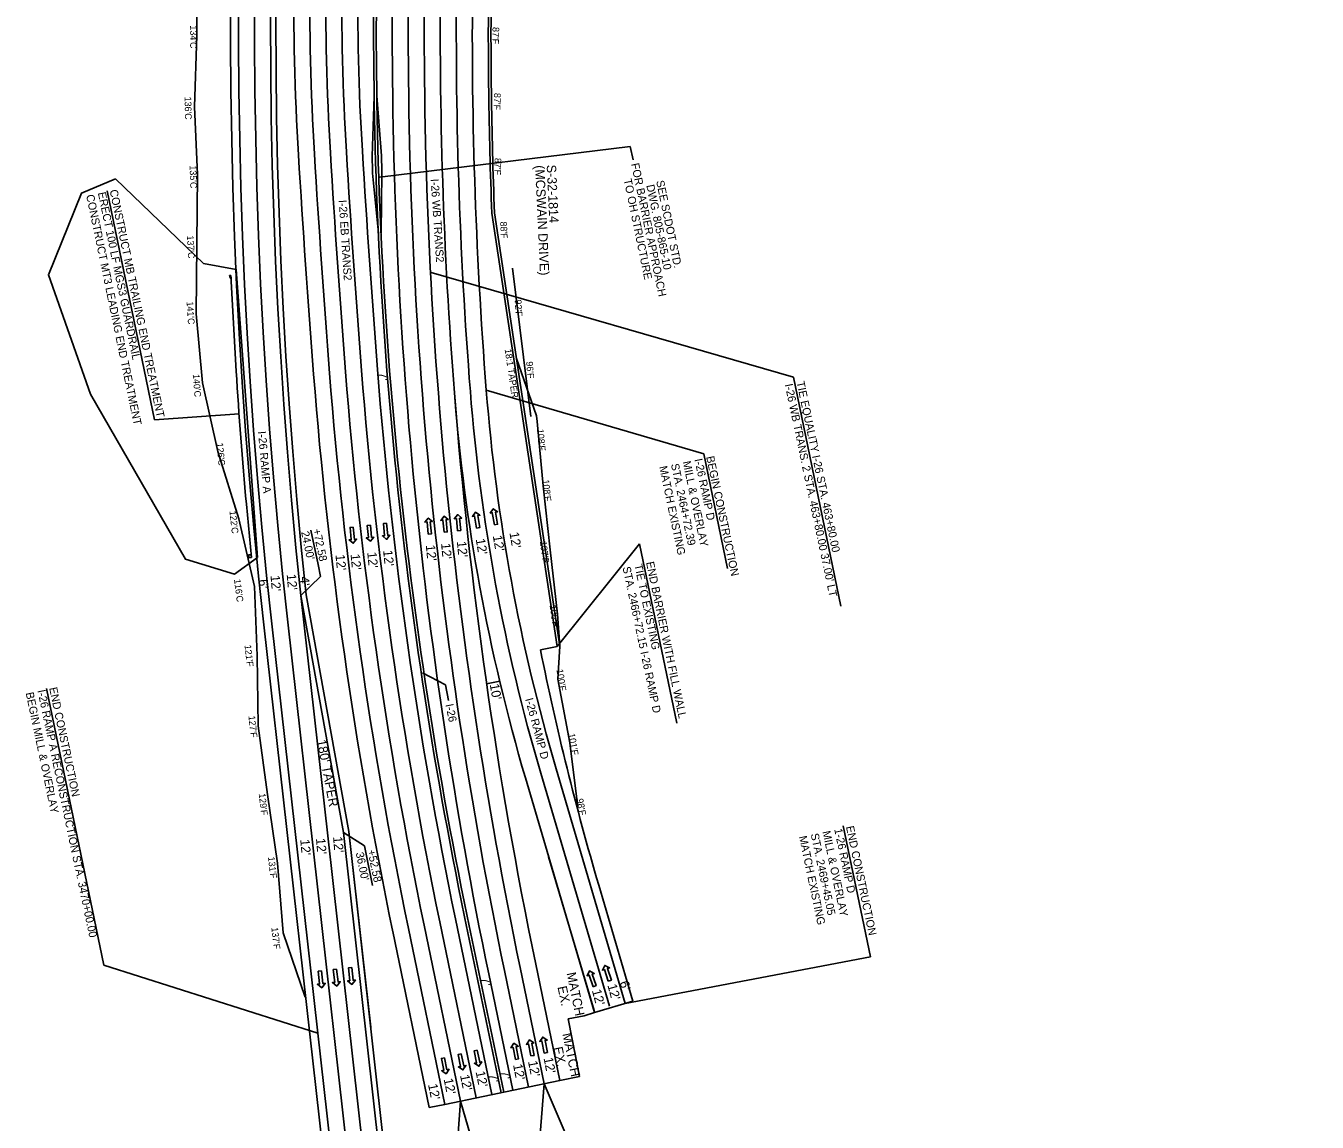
# Model space of a CAD drawing. Extents: x 1966090 to 1975830, y 788086 to 801233.
# Drawn here: x 1966139 to 1967107, y 790071 to 790893 of the extents above; entities that cross this region are included whole.
import ezdxf

# ---------------------------------------------------------------- set-up
doc = ezdxf.new("R2010")
doc.units = 0
for name, color, linetype in [('BR_PRESTRESSED BEAM', 7, 'Continuous'), ('BR_PROPOSED_DRAINAGE', 7, 'Continuous'), ('BR_REBAR', 7, 'Continuous'), ('RD_EX_Driveway_txCode', 7, 'Continuous'), ('RD_EX_RW_TX', 7, 'Continuous'), ('RD_EX_SU_Gas', 7, 'Continuous'), ('RD_EX_SU_H2O', 7, 'Continuous'), ('RD_EX_TX_Dam_ELEV', 7, 'Continuous'), ('RD_PD_PaveShd', 7, 'Continuous'), ('RD_PD_SuperShp1', 7, 'Continuous'), ('RD_Sketch6', 7, 'Continuous'), ('RD_Sketch8', 7, 'Continuous'), ('RD_Sketch9', 7, 'Continuous')]:
    doc.layers.add(name, color=color, linetype=linetype)

msp = doc.modelspace()

# ---------------------------------------------------------------- linework, layer by layer
at = {"layer": 'BR_PRESTRESSED BEAM'}
for p, q in [((1966292.45, 790706.34), (1966291.45, 790706.29)), ((1966291.45, 790706.29), (1966291.81, 790704.3)), ((1966291.81, 790704.3), (1966292.56, 790704.34)), ((1966292.56, 790704.34), (1966292.45, 790706.34)), ((1966296.41, 790634.45), (1966292.45, 790706.34)), ((1966304.05, 790534.75), (1966307.79, 790494.92)), ((1966305.62, 790496.73), (1966307.61, 790496.91)), ((1966305.8, 790494.73), (1966305.62, 790496.73)), ((1966307.79, 790494.92), (1966305.8, 790494.73)), ((1966307.61, 790496.91), (1966307.79, 790494.92))]:
    msp.add_line(p, q, dxfattribs=at)
msp.add_arc((1970298.2, 790890.83), 4010, 183.66575, 185.09457, dxfattribs=at)
at = {"layer": 'BR_PROPOSED_DRAINAGE'}
for p, q in [((1966266.74, 790938.12), (1966266.94, 790886.07)), ((1966266.94, 790886.07), (1966265.15, 790832.72)), ((1966265.15, 790832.72), (1966267.55, 790781.98)), ((1966267.55, 790781.98), (1966266.81, 790729.83)), ((1966266.81, 790729.83), (1966266.32, 790677.6)), ((1966266.32, 790677.6), (1966271.12, 790625.67)), ((1966506.51, 790643.98), (1966521.65, 790601.14)), ((1966271.12, 790625.67), (1966282.76, 790574.4)), ((1966522.03, 790596.69), (1966521.65, 790601.14)), ((1966522.03, 790596.69), (1966526.49, 790548.54)), ((1966282.76, 790574.4), (1966298.32, 790523.77)), ((1966526.49, 790548.54), (1966531.89, 790500.48)), ((1966298.32, 790523.77), (1966310.04, 790472.96)), ((1966531.89, 790500.48), (1966537.32, 790452.41)), ((1966312.26, 790421), (1966310.04, 790472.96)), ((1966537.32, 790452.41), (1966538.93, 790428.43)), ((1966538.93, 790428.43), (1966537.61, 790403.5)), ((1966312.26, 790421), (1966312.94, 790368.64)), ((1966537.61, 790403.5), (1966546.57, 790355.85)), ((1966312.94, 790368.64), (1966319.93, 790317.13)), ((1966546.57, 790355.85), (1966552.65, 790307.69)), ((1966319.93, 790317.13), (1966327.47, 790265.67)), ((1966331.56, 790213.45), (1966327.47, 790265.67)), ((1966348.13, 790165.17), (1966331.56, 790213.45))]:
    msp.add_line(p, q, dxfattribs=at)
msp.add_arc((1969885.93, 790887.47), 3398.48, 179.19823, 182.26832, dxfattribs=at)
at = {"layer": 'BR_REBAR'}
for p, q in [((1966488.12, 790752.88), (1966536.95, 790428.14)), ((1966538.93, 790428.43), (1966490.09, 790753.18))]:
    msp.add_line(p, q, dxfattribs=at)
for radius, end in [(3400.48, 182.26832), (3398.48, 182.2663)]:
    msp.add_arc((1969885.93, 790887.47), radius, 179.19823, end, dxfattribs=at)
at = {"layer": 'RD_EX_Driveway_txCode'}
for points in [[(1966489.97, 790519.35), (1966492.33, 790519.75), (1966490.8, 790528.79), (1966492.4, 790529.06), (1966489.14, 790531.38), (1966486.83, 790528.12), (1966488.43, 790528.39)], [(1966409.21, 790520.47), (1966406.82, 790520.24), (1966407.71, 790511.11), (1966406.09, 790510.95), (1966409.17, 790508.41), (1966411.72, 790511.5), (1966410.1, 790511.34)], [(1966440.41, 790512.31), (1966442.8, 790512.54), (1966441.92, 790521.67), (1966443.54, 790521.83), (1966440.45, 790524.37), (1966437.91, 790521.28), (1966439.53, 790521.44)], [(1966452.24, 790513.7), (1966454.63, 790513.93), (1966453.74, 790523.06), (1966455.36, 790523.21), (1966452.27, 790525.75), (1966449.73, 790522.67), (1966451.35, 790522.82)], [(1966462.44, 790514.89), (1966464.83, 790515.12), (1966463.95, 790524.25), (1966465.57, 790524.41), (1966462.48, 790526.95), (1966459.94, 790523.86), (1966461.56, 790524.02)], [(1966476.7, 790516.82), (1966479.06, 790517.22), (1966477.53, 790526.27), (1966479.13, 790526.54), (1966475.87, 790528.85), (1966473.56, 790525.59), (1966475.16, 790525.86)], [(1966384.23, 790517.55), (1966381.84, 790517.31), (1966382.73, 790508.19), (1966381.11, 790508.03), (1966384.2, 790505.49), (1966386.74, 790508.57), (1966385.12, 790508.42)], [(1966397.05, 790519.05), (1966394.66, 790518.81), (1966395.54, 790509.69), (1966393.92, 790509.53), (1966397.01, 790506.99), (1966399.55, 790510.07), (1966397.93, 790509.92)], [(1966360.43, 790184.88), (1966357.92, 790184.6), (1966359, 790175.03), (1966357.3, 790174.84), (1966360.58, 790172.22), (1966363.2, 790175.5), (1966361.5, 790175.31)], [(1966371.73, 790186.11), (1966369.22, 790185.83), (1966370.3, 790176.26), (1966368.6, 790176.07), (1966371.88, 790173.45), (1966374.5, 790176.73), (1966372.8, 790176.54)], [(1966383.03, 790187.35), (1966380.53, 790187.07), (1966381.6, 790177.5), (1966379.9, 790177.31), (1966383.18, 790174.69), (1966385.8, 790177.97), (1966384.1, 790177.78)], [(1966563.94, 790173.02), (1966566.21, 790173.78), (1966563.31, 790182.48), (1966564.85, 790183), (1966561.28, 790184.79), (1966559.49, 790181.21), (1966561.03, 790181.72)], [(1966575.41, 790177.15), (1966577.68, 790177.91), (1966574.78, 790186.61), (1966576.32, 790187.13), (1966572.74, 790188.91), (1966570.96, 790185.34), (1966572.5, 790185.85)], [(1966517.36, 790121.06), (1966519.71, 790121.53), (1966517.94, 790130.53), (1966519.54, 790130.84), (1966516.22, 790133.07), (1966513.99, 790129.75), (1966515.59, 790130.06)], [(1966527.4, 790123.25), (1966529.75, 790123.71), (1966527.98, 790132.71), (1966529.58, 790133.03), (1966526.26, 790135.25), (1966524.03, 790131.93), (1966525.63, 790132.25)], [(1966477.11, 790125.34), (1966474.76, 790124.85), (1966476.61, 790115.87), (1966475.01, 790115.54), (1966478.36, 790113.34), (1966480.55, 790116.68), (1966478.96, 790116.35)], [(1966505.73, 790118.53), (1966508.08, 790119), (1966506.31, 790127.99), (1966507.91, 790128.31), (1966504.59, 790130.54), (1966502.36, 790127.22), (1966503.95, 790127.53)], [(1966452.58, 790119.77), (1966450.23, 790119.28), (1966452.09, 790110.3), (1966450.49, 790109.97), (1966453.83, 790107.77), (1966456.03, 790111.11), (1966454.44, 790110.78)], [(1966465.16, 790122.62), (1966462.81, 790122.14), (1966464.67, 790113.16), (1966463.07, 790112.83), (1966466.41, 790110.63), (1966468.61, 790113.97), (1966467.02, 790113.64)]]:
    msp.add_lwpolyline(points, close=True, dxfattribs=at)
at = {"layer": 'RD_EX_SU_Gas'}
for p, q in [((1966344.94, 790466.24), (1966365.1, 790286.08)), ((1966335.05, 790446.36), (1966394.18, 789919.16)), ((1966576.18, 790158.46), (1966524.78, 790333.01)), ((1966365.1, 790286.08), (1966407.24, 789910.32)), ((1966449.07, 790221.57), (1966476.42, 790089.64)), ((1966437.32, 790219.13), (1966464.67, 790087.2)), ((1966497.5, 790185.03), (1966515.59, 790097.76)), ((1966509.25, 790187.47), (1966527.34, 790100.2))]:
    msp.add_line(p, q, dxfattribs=at)
for centre, radius, start, end in [((1970298.2, 790890.83), 3988, 153.13743, 186.39908), ((1968216.27, 790910.84), 1852.65, 179.19823, 183.4866), ((1968216.27, 790910.84), 1840.65, 179.19823, 183.4866), ((1969885.93, 790887.47), 3460.48, 179.19823, 191.71175), ((1969885.93, 790887.47), 3448.48, 179.19823, 191.71175), ((1969885.93, 790887.47), 3436.48, 179.19823, 184.49115), ((1969885.93, 790887.47), 3424.48, 179.19823, 184.49115), ((1976168.37, 791395.34), 9819.5, 183.486596, 184.446699), ((1976168.37, 791395.34), 9807.5, 183.486596, 184.446699), ((1969675.47, 790890.41), 3307, 184.4467, 191.71174), ((1969675.47, 790890.41), 3295, 184.4467, 191.71174), ((1967869.66, 790729.1), 1402, 184.49115, 196.41034)]:
    msp.add_arc(centre, radius, start, end, dxfattribs=at)
at = {"layer": 'RD_EX_TX_Dam_ELEV'}
msp.add_line((1966503.57, 790711.69), (1966517.4, 790600.5), dxfattribs=at)
at = {"layer": 'RD_PD_PaveShd'}
for p, q in [((1966488.12, 790752.88), (1966536.95, 790428.14)), ((1966348.9, 790466.81), (1966380.84, 790289.27)), ((1966351.58, 790137.51), (1966317.16, 790444.35)), ((1966524.49, 790425.61), (1966536.95, 790428.14)), ((1966380.84, 790289.27), (1966419.87, 789941.3)), ((1966380.86, 790289.14), (1966397.29, 790142.64)), ((1966593.88, 790162.07), (1966568.26, 790249.06)), ((1966467.68, 790225.43), (1966495.02, 790093.5)), ((1966469.63, 790225.83), (1966496.98, 790093.9)), ((1966413.82, 790214.26), (1966441.17, 790082.33)), ((1966557.19, 790151.26), (1966565.11, 790153.6)), ((1966557.19, 790151.26), (1966545.28, 790149.01)), ((1966545.28, 790149.01), (1966553.88, 790105.7)), ((1966351.58, 790137.51), (1966361.05, 790053.05)), ((1966539.09, 790102.63), (1966553.88, 790105.7)), ((1966441.17, 790082.33), (1966452.92, 790084.77))]:
    msp.add_line(p, q, dxfattribs=at)
for centre, radius, start, end in [((1970298.2, 790890.83), 4006, 153.13743, 186.39908), ((1970298.2, 790890.83), 3972, 153.13743, 186.12823), ((1968216.27, 790910.84), 1876.65, 179.19823, 183.4866), ((1969675.47, 790890.41), 3276, 179.19823, 191.71174), ((1969675.47, 790890.41), 3274, 179.19823, 191.71174), ((1969885.93, 790887.47), 3400.48, 179.19823, 182.26832), ((1976168.37, 791395.34), 9843.5, 183.486596, 184.446699), ((1969675.47, 790890.41), 3331, 184.4467, 191.71174), ((1968581.67, 790842.04), 2098.91, 191.44335, 196.41034)]:
    msp.add_arc(centre, radius, start, end, dxfattribs=at)
at = {"layer": 'RD_PD_SuperShp1'}
msp.add_arc((1966773.27, 790734.61), 333.52, 177.18598, 177.18598, dxfattribs=at)
at = {"layer": 'RD_Sketch6'}
for p, q in [((1966404.24, 790780.02), (1966591.86, 790803.08)), ((1966591.86, 790803.08), (1966593.94, 790793.05)), ((1966199.71, 790769.65), (1966235.3, 790597.94)), ((1966442.59, 790708.42), (1966714.13, 790630.02)), ((1966749.72, 790458.33), (1966714.13, 790630.02)), ((1966483.93, 790620.25), (1966646.89, 790572.41)), ((1966235.3, 790597.94), (1966298.58, 790602.58)), ((1966664.67, 790486.67), (1966646.89, 790572.41)), ((1966357.79, 790489.56), (1966352.43, 790515.39)), ((1966536.95, 790428.14), (1966598.88, 790505.15)), ((1966626.79, 790370.55), (1966598.88, 790505.15)), ((1966453.22, 790399.4), (1966436.16, 790408.29)), ((1966197.29, 790189.17), (1966154.28, 790396.65)), ((1966455.66, 790387.65), (1966453.22, 790399.4)), ((1966771.88, 790195.49), (1966751.55, 790293.58)), ((1966398.7, 790248.98), (1966393.35, 790274.79)), ((1966588.13, 790160.38), (1966771.88, 790195.49)), ((1966197.29, 790189.17), (1966357.54, 790138.18)), ((1966527.34, 790100.2), (1966523.42, 790049.75)), ((1966527.34, 790100.2), (1966546.86, 790054.61)), ((1966464.67, 790087.2), (1966460.76, 790036.76)), ((1966464.67, 790087.2), (1966478.16, 790040.37))]:
    msp.add_line(p, q, dxfattribs=at)
msp.add_lwpolyline([(1966206.07, 790778.74), (1966271.87, 790715.28), (1966296.53, 790710.75), (1966312.4, 790494.86), (1966295.26, 790482.37), (1966258.55, 790493.51), (1966187.27, 790617.31), (1966155.72, 790706.63), (1966180.52, 790768.04)], close=True, dxfattribs=at)
for points in [[(1966357.79, 790489.56), (1966359.65, 790480.61), (1966344.94, 790466.24)], [(1966393.35, 790274.79), (1966392.58, 790278.51), (1966376.88, 790288.69)]]:
    msp.add_lwpolyline(points, dxfattribs=at)
at = {"layer": 'RD_Sketch8'}
for p, q in [((1966344.94, 790466.24), (1966376.88, 790288.69)), ((1966367.01, 790053.72), (1966323.13, 790445.02)), ((1966494.02, 790401.98), (1966484.2, 790400.12)), ((1966588.13, 790160.38), (1966536.29, 790336.4)), ((1966565.11, 790153.6), (1966513.26, 790329.62)), ((1966376.88, 790288.69), (1966417.86, 789923.34)), ((1966564.67, 790155.07), (1966530.68, 790270.49)), ((1966460.82, 790224), (1966488.17, 790092.08)), ((1966425.57, 790216.7), (1966452.92, 790084.77)), ((1966485.75, 790182.6), (1966503.84, 790095.32)), ((1966521, 790189.9), (1966539.09, 790102.63)), ((1966593.88, 790162.07), (1966565.11, 790153.6)), ((1966452.92, 790084.77), (1966539.09, 790102.63))]:
    msp.add_line(p, q, dxfattribs=at)
for centre, radius, start, end in [((1970298.2, 790890.83), 4000, 153.13743, 186.39908), ((1970298.2, 790890.83), 3976, 153.13743, 186.13028), ((1968216.27, 790910.84), 1864.65, 179.19823, 183.4866), ((1968216.27, 790910.84), 1828.65, 179.19823, 183.4866), ((1969885.93, 790887.47), 3472.48, 179.19823, 191.71175), ((1969885.93, 790887.47), 3412.48, 179.19823, 184.49115), ((1976168.37, 791395.34), 9831.5, 183.486596, 184.446699), ((1976168.37, 791395.34), 9795.5, 183.486596, 184.446699), ((1969675.47, 790890.41), 3283, 184.4467, 191.71174), ((1969675.47, 790890.41), 3319, 184.4467, 191.71174), ((1969885.93, 790887.47), 3436.48, 184.49115, 191.71175), ((1967869.66, 790729.1), 1414, 184.49115, 196.41034), ((1967869.66, 790729.1), 1390, 184.49115, 196.41034)]:
    msp.add_arc(centre, radius, start, end, dxfattribs=at)
at = {"layer": 'RD_Sketch9'}
for p, q in [((1966399.85, 790840.81), (1966398.34, 790795.73)), ((1966405.34, 790795.94), (1966401.85, 790840.84)), ((1966403.02, 790738.11), (1966398.73, 790783)), ((1966405.73, 790783.23), (1966405.01, 790738.2))]:
    msp.add_line(p, q, dxfattribs=at)
for radius in [3278.5, 3271.5]:
    msp.add_arc((1969675.47, 790890.41), radius, 181.6549, 181.87746, dxfattribs=at)

# ---------------------------------------------------------------- texts
at = {"layer": 'RD_EX_Driveway_txCode'}
for s, height, rotation, p in [("7'", 7, 276.89395, (1966402.63, 790633.59)), ('I-26 RAMP A', 5.9996, 274.79242, (1966312.79, 790589.33)), ("12'", 7, 279.6416, (1966488.78, 790510.98)), ("12'", 7, 279.6416, (1966501.26, 790513.35)), ("12'", 7, 275.53712, (1966438.56, 790504.04)), ("12'", 7, 275.53712, (1966449.99, 790505.37)), ("12'", 7, 275.53712, (1966461.84, 790506.76)), ("12'", 7, 279.6416, (1966475.96, 790508.53)), ("12'", 7, 275.53712, (1966370.83, 790496.86)), ("12'", 7, 275.53712, (1966382.15, 790497.24)), ("12'", 7, 275.53712, (1966394.64, 790498.7)), ("12'", 7, 275.53712, (1966406.57, 790500.1)), ("12'", 7, 274.9047, (1966322.14, 790481.27)), ("12'", 7, 274.9047, (1966334.27, 790482.22)), ("6'", 7, 274.9047, (1966313.09, 790478.21)), ("4'", 7, 274.9047, (1966344.11, 790480.26)), ("10'", 7, 280.19127, (1966486.47, 790399.62)), ('I-26 RAMP D', 5.9996, 284.97228, (1966512.99, 790388.62)), ("180' TAPER", 7, 280.55636, (1966356.85, 790357.67)), ("12'", 7, 274.9047, (1966344.44, 790283.33)), ("12'", 7, 274.9047, (1966356.23, 790284.09)), ("12'", 7, 274.9047, (1966369.03, 790285.33)), ('MATCH ', 7, 281.71174, (1966544.06, 790183.11)), ("7'", 7, 281.13985, (1966479.6, 790179.63)), ('EX.', 7, 281.71174, (1966537.26, 790172.79)), ("12'", 7, 285.29537, (1966574.69, 790174.07)), ("6'", 7, 285.29537, (1966583.74, 790176.31)), ("12'", 7, 285.29537, (1966563.01, 790170.1)), ('MATCH ', 7, 281.71174, (1966540.88, 790137.57)), ('EX.', 7, 281.71174, (1966534.09, 790127.25)), ("12'", 7, 281.13985, (1966503.92, 790114.45)), ("12'", 7, 281.13985, (1966515.16, 790116.89)), ("12'", 7, 281.13985, (1966526.82, 790119.43)), ("12'", 7, 281.65632, (1966451.9, 790103.68)), ("12'", 7, 281.65632, (1966464.17, 790106.47)), ("12'", 7, 281.65632, (1966475.88, 790109.13)), ("7'", 7, 281.13985, (1966485.32, 790107.3)), ("7'", 7, 281.13985, (1966494.1, 790109.66)), ("12'", 7, 281.65632, (1966440.2, 790099.58))]:
    msp.add_text(s, height=height, rotation=rotation, dxfattribs=at).set_placement(p)
at = {"layer": 'RD_EX_RW_TX'}
for s, rotation, p in [("134'C", 270.07298, (1966261.93, 790893.73)), ("87'F", 268.32349, (1966488.66, 790892.59)), ("136'C", 270.94772, (1966257.79, 790840.32)), ("87'F", 268.32349, (1966489.82, 790843.19)), ("87'F", 268.32349, (1966490.21, 790794.43)), ("135'C", 271.82246, (1966261.52, 790788.73)), ("88'F", 272.69721, (1966494.34, 790746.6)), ("137'C", 272.69721, (1966259.57, 790736.12)), ("141'C", 273.57195, (1966259.27, 790686.61)), ("92'F", 273.57195, (1966505.24, 790688.02)), ('18:1 TAPER', 278.4168, (1966497.67, 790650.83)), ("96'F", 274.4467, (1966513.82, 790641.62)), ("140'C", 274.4467, (1966263.88, 790632.15)), ("108'F", 275.32144, (1966521.9, 790590.96)), ("126'C", 275.32144, (1966281.65, 790580.64)), ("108'F", 276.19619, (1966525.97, 790552.97)), ("122'C", 276.19619, (1966291.36, 790529.64)), ("107'F", 277.07093, (1966524.12, 790506.86)), ("116'C", 277.07093, (1966294.81, 790478.31)), ("106'F", 277.94568, (1966531.38, 790458.94)), ("121'F", 276.39908, (1966302.68, 790429.06)), ("100'F", 278.82042, (1966536.49, 790410.71)), ("127'F", 276.39908, (1966305.58, 790375.92)), ("101'F", 279.69517, (1966545.43, 790362.57)), ("129'F", 276.39908, (1966313.33, 790317.69)), ("98'F", 280.56991, (1966551.55, 790313.62)), ("131'F", 276.39908, (1966320.24, 790270.24)), ("137'F", 276.39908, (1966322.78, 790217.23))]:
    msp.add_text(s, height=5, rotation=rotation, dxfattribs=at).set_placement(p)
at = {"layer": 'RD_EX_SU_H2O'}
for s, height, rotation, p in [('(MCSWAIN DRIVE)', 7, 272.60739, (1966520.47, 790788.77)), ('S-32-1814 ', 7, 272.60739, (1966529.21, 790789.17)), ('I-26 WB TRANS2', 5.9996, 273.73863, (1966442.24, 790778.59)), ('I-26 EB TRANS2', 5.9996, 273.73863, (1966373.26, 790762.74))]:
    msp.add_text(s, height=height, rotation=rotation, dxfattribs=at).set_placement(p)
at = {"layer": 'RD_Sketch6'}
for s, height, rotation, p in [('FOR BARRIER APPROACH ', 6, 281.71181, (1966592.47, 790789.92)), ('TO OH STRUCTURE', 6, 281.71181, (1966586.87, 790778.16)), ('DWG. 805-865-10', 6, 281.71181, (1966603.84, 790773.83)), ('SEE SCDOT STD. ', 6, 281.71181, (1966611.22, 790776.94)), ('CONSTRUCT MT3 LEADING END TREATMENT', 5.9996, 281.73841, (1966183.9, 790766.37)), ('ERECT 100 LF MGS3 GUARDRAIL', 5.9996, 281.73841, (1966192.71, 790768.2)), ('CONSTRUCT MB TRAILING END TREATMENT', 5.9996, 281.73841, (1966201.53, 790770.03)), ('TIE EQUALITY I-26 STA. 463+80.00', 5.9996, 281.8716, (1966716.45, 790626.32)), ("I-26 WB TRANS. 2 STA. 463+80.00 37.00' LT", 5.9996, 281.8716, (1966707.64, 790624.47)), ('I-26 RAMP D', 5.9996, 281.8716, (1966639.93, 790568.38)), ('BEGIN CONSTRUCTION', 5.9996, 281.8716, (1966648.74, 790570.24)), ('MATCH EXISTING', 5.9996, 281.8716, (1966613.51, 790562.83)), ('STA. 2464+72.39', 5.9996, 281.8716, (1966622.32, 790564.68)), ('MILL & OVERLAY', 5.9996, 281.8716, (1966631.13, 790566.53)), ("24.00'", 6, 281.71177, (1966345.09, 790513.87)), ('+72.58', 6, 281.71177, (1966353.9, 790515.69)), ('END BARRIER WITH FILL WALL', 5.9996, 281.8716, (1966603.65, 790491.1)), ('STA. 2466+72.15 I-26 RAMP D', 5.9996, 281.8716, (1966586.04, 790487.4)), ('TIE TO EXISTING', 5.9996, 281.8716, (1966594.84, 790489.25)), ('BEGIN MILL & OVERLAY ', 5.9996, 281.8716, (1966138.6, 790393.21)), ('I-26 RAMP A RECONSTRUCTION STA. 3470+00.00', 5.9996, 281.8716, (1966147.41, 790395.07)), ('END CONSTRUCTION', 5.9996, 281.8716, (1966156.21, 790396.92)), ('I-26', 6, 281.71177, (1966453.25, 790384.48)), ('STA. 2469+45.05', 5.9996, 281.8716, (1966727.1, 790287.38)), ('MILL & OVERLAY', 5.9996, 281.8716, (1966735.9, 790289.23)), ('1-26 RAMP D', 5.9996, 281.8716, (1966744.71, 790291.08)), ('END CONSTRUCTION', 5.9996, 281.8716, (1966753.52, 790292.93)), ('MATCH EXISTING', 5.9996, 281.8716, (1966718.29, 790285.52)), ("36.00'", 6, 281.71177, (1966386.01, 790273.26)), ('+52.58', 6, 281.71177, (1966394.82, 790275.09))]:
    msp.add_text(s, height=height, rotation=rotation, dxfattribs=at).set_placement(p)

doc.saveas('drawing.dxf')
